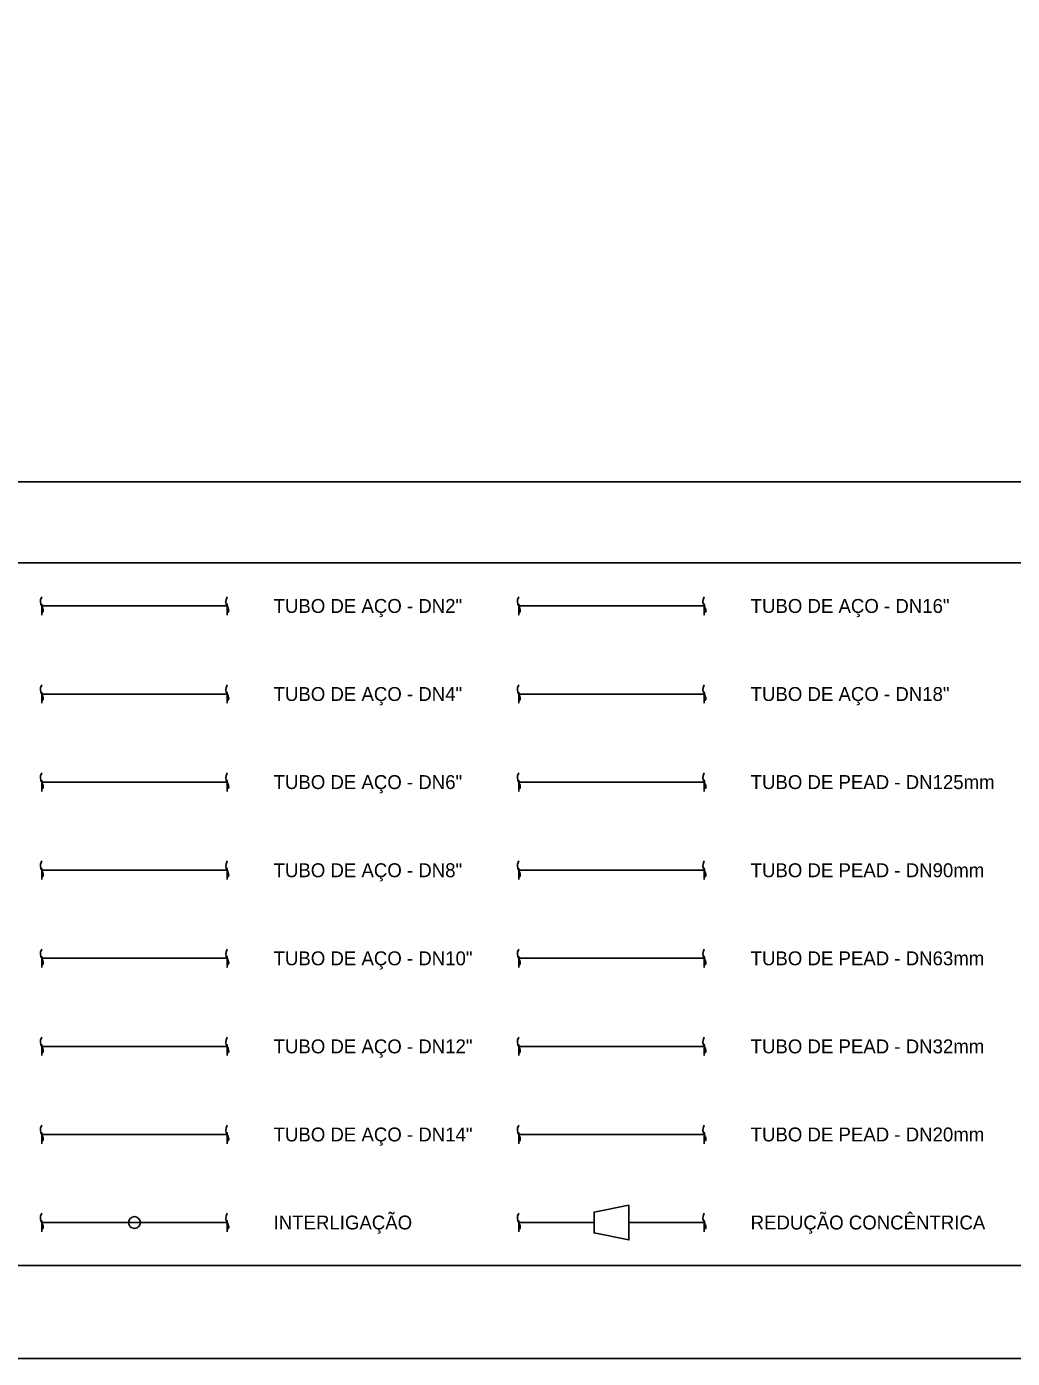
# Model space of a CAD drawing. Extents: x -1349 to -508, y 286 to 880.
# Drawn here: x -1137.7 to -1031.4, y 285.8 to 429.5 of the extents above; entities that cross this region are included whole.
import ezdxf

# ---------------------------------------------------------------- set-up
doc = ezdxf.new("R2010")
doc.units = 0
for name, color, linetype in [('FORMATO', 7, 'Continuous'), ('LEGENDA', 7, 'Continuous'), ('TUBO_ACO_GN_10', 7, 'Continuous'), ('TUBO_ACO_GN_12', 7, 'Continuous'), ('TUBO_ACO_GN_14', 7, 'Continuous'), ('TUBO_ACO_GN_16', 7, 'Continuous'), ('TUBO_ACO_GN_18', 7, 'Continuous'), ('TUBO_ACO_GN_2', 7, 'Continuous'), ('TUBO_ACO_GN_4', 7, 'Continuous'), ('TUBO_ACO_GN_6', 7, 'Continuous'), ('TUBO_ACO_GN_8', 7, 'Continuous'), ('TUBO_PEAD_GN_125', 7, 'Continuous'), ('TUBO_PEAD_GN_20', 7, 'Continuous'), ('TUBO_PEAD_GN_32', 7, 'Continuous'), ('TUBO_PEAD_GN_63', 7, 'Continuous'), ('TUBO_PEAD_GN_90', 7, 'Continuous')]:
    doc.layers.add(name, color=color, linetype=linetype)

msp = doc.modelspace()

# ---------------------------------------------------------------- linework, layer by layer
at = {"layer": 'FORMATO'}
msp.add_line((-518.04, 295.82), (-1344.05, 295.82), dxfattribs=at)
msp.add_lwpolyline([(-1349.05, 879.82), (-508.05, 879.82), (-508.05, 285.82), (-1349.05, 285.82)], close=True, dxfattribs=at)
for points in [[(-518.04, 380.36), (-1324.05, 380.36)], [(-1324.05, 371.63), (-693.05, 371.63)]]:
    msp.add_lwpolyline(points, dxfattribs=at)
at = {"layer": 'LEGENDA'}
msp.add_lwpolyline([(-1072.74, 302.34), (-1076.49, 301.59), (-1076.49, 299.34), (-1072.74, 298.59)], close=True, dxfattribs=at)
for points in [[(-1136.05, 300.47), (-1116.05, 300.47)], [(-1084.62, 300.47), (-1076.49, 300.47)], [(-1072.74, 300.47), (-1064.62, 300.47)]]:
    msp.add_lwpolyline(points, dxfattribs=at)
msp.add_circle((-1126.05, 300.47), 0.633, dxfattribs=at)
for points in [[(-1136.05, 301.47), (-1136.3, 300.97), (-1136.05, 300.47), (-1135.8, 299.97), (-1136.05, 299.47), (-1136.05, 301.47), (-1136.05, 299.47)], [(-1116.05, 301.47), (-1116.3, 300.97), (-1116.05, 300.47), (-1115.8, 299.97), (-1116.05, 299.47), (-1116.05, 301.47), (-1116.05, 299.47)], [(-1084.62, 301.47), (-1084.87, 300.97), (-1084.62, 300.47), (-1084.37, 299.97), (-1084.62, 299.47), (-1084.62, 301.47), (-1084.62, 299.47)], [(-1064.62, 301.47), (-1064.87, 300.97), (-1064.62, 300.47), (-1064.37, 299.97), (-1064.62, 299.47), (-1064.62, 301.47), (-1064.62, 299.47)]]:
    msp.add_open_spline(points, degree=3, dxfattribs=at)
at = {"layer": 'TUBO_ACO_GN_10'}
msp.add_lwpolyline([(-1136.05, 328.97), (-1116.05, 328.97)], dxfattribs=at)
for points in [[(-1136.05, 329.97), (-1136.3, 329.47), (-1136.05, 328.97), (-1135.8, 328.47), (-1136.05, 327.97), (-1136.05, 329.97), (-1136.05, 327.97)], [(-1116.05, 329.97), (-1116.3, 329.47), (-1116.05, 328.97), (-1115.8, 328.47), (-1116.05, 327.97), (-1116.05, 329.97), (-1116.05, 327.97)]]:
    msp.add_open_spline(points, degree=3, dxfattribs=at)
at = {"layer": 'TUBO_ACO_GN_12'}
msp.add_lwpolyline([(-1136.05, 319.47), (-1116.05, 319.47)], dxfattribs=at)
for points in [[(-1136.05, 320.47), (-1136.3, 319.97), (-1136.05, 319.47), (-1135.8, 318.97), (-1136.05, 318.47), (-1136.05, 320.47), (-1136.05, 318.47)], [(-1116.05, 320.47), (-1116.3, 319.97), (-1116.05, 319.47), (-1115.8, 318.97), (-1116.05, 318.47), (-1116.05, 320.47), (-1116.05, 318.47)]]:
    msp.add_open_spline(points, degree=3, dxfattribs=at)
at = {"layer": 'TUBO_ACO_GN_14'}
msp.add_lwpolyline([(-1136.05, 309.97), (-1116.05, 309.97)], dxfattribs=at)
for points in [[(-1136.05, 310.97), (-1136.3, 310.47), (-1136.05, 309.97), (-1135.8, 309.47), (-1136.05, 308.97), (-1136.05, 310.97), (-1136.05, 308.97)], [(-1116.05, 310.97), (-1116.3, 310.47), (-1116.05, 309.97), (-1115.8, 309.47), (-1116.05, 308.97), (-1116.05, 310.97), (-1116.05, 308.97)]]:
    msp.add_open_spline(points, degree=3, dxfattribs=at)
at = {"layer": 'TUBO_ACO_GN_16'}
msp.add_lwpolyline([(-1084.62, 366.98), (-1064.62, 366.98)], dxfattribs=at)
for points in [[(-1084.62, 367.98), (-1084.87, 367.48), (-1084.62, 366.98), (-1084.37, 366.48), (-1084.62, 365.98), (-1084.62, 367.98), (-1084.62, 365.98)], [(-1064.62, 367.98), (-1064.87, 367.48), (-1064.62, 366.98), (-1064.37, 366.48), (-1064.62, 365.98), (-1064.62, 367.98), (-1064.62, 365.98)]]:
    msp.add_open_spline(points, degree=3, dxfattribs=at)
at = {"layer": 'TUBO_ACO_GN_18'}
msp.add_lwpolyline([(-1084.62, 357.48), (-1064.62, 357.48)], dxfattribs=at)
for points in [[(-1084.62, 358.48), (-1084.87, 357.98), (-1084.62, 357.48), (-1084.37, 356.98), (-1084.62, 356.48), (-1084.62, 358.48), (-1084.62, 356.48)], [(-1064.62, 358.48), (-1064.87, 357.98), (-1064.62, 357.48), (-1064.37, 356.98), (-1064.62, 356.48), (-1064.62, 358.48), (-1064.62, 356.48)]]:
    msp.add_open_spline(points, degree=3, dxfattribs=at)
at = {"layer": 'TUBO_ACO_GN_2'}
msp.add_lwpolyline([(-1136.05, 366.98), (-1116.05, 366.98)], dxfattribs=at)
for points in [[(-1136.05, 367.98), (-1136.3, 367.48), (-1136.05, 366.98), (-1135.8, 366.48), (-1136.05, 365.98), (-1136.05, 367.98), (-1136.05, 365.98)], [(-1116.05, 367.98), (-1116.3, 367.48), (-1116.05, 366.98), (-1115.8, 366.48), (-1116.05, 365.98), (-1116.05, 367.98), (-1116.05, 365.98)]]:
    msp.add_open_spline(points, degree=3, dxfattribs=at)
at = {"layer": 'TUBO_ACO_GN_4'}
msp.add_lwpolyline([(-1136.05, 357.48), (-1116.05, 357.48)], dxfattribs=at)
for points in [[(-1136.05, 358.48), (-1136.3, 357.98), (-1136.05, 357.48), (-1135.8, 356.98), (-1136.05, 356.48), (-1136.05, 358.48), (-1136.05, 356.48)], [(-1116.05, 358.48), (-1116.3, 357.98), (-1116.05, 357.48), (-1115.8, 356.98), (-1116.05, 356.48), (-1116.05, 358.48), (-1116.05, 356.48)]]:
    msp.add_open_spline(points, degree=3, dxfattribs=at)
at = {"layer": 'TUBO_ACO_GN_6'}
msp.add_lwpolyline([(-1136.05, 347.98), (-1116.05, 347.98)], dxfattribs=at)
for points in [[(-1136.05, 348.98), (-1136.3, 348.48), (-1136.05, 347.98), (-1135.8, 347.48), (-1136.05, 346.98), (-1136.05, 348.98), (-1136.05, 346.98)], [(-1116.05, 348.98), (-1116.3, 348.48), (-1116.05, 347.98), (-1115.8, 347.48), (-1116.05, 346.98), (-1116.05, 348.98), (-1116.05, 346.98)]]:
    msp.add_open_spline(points, degree=3, dxfattribs=at)
at = {"layer": 'TUBO_ACO_GN_8'}
msp.add_lwpolyline([(-1136.05, 338.47), (-1116.05, 338.47)], dxfattribs=at)
for points in [[(-1136.05, 339.47), (-1136.3, 338.97), (-1136.05, 338.47), (-1135.8, 337.97), (-1136.05, 337.47), (-1136.05, 339.47), (-1136.05, 337.47)], [(-1116.05, 339.47), (-1116.3, 338.97), (-1116.05, 338.47), (-1115.8, 337.97), (-1116.05, 337.47), (-1116.05, 339.47), (-1116.05, 337.47)]]:
    msp.add_open_spline(points, degree=3, dxfattribs=at)
at = {"layer": 'TUBO_PEAD_GN_125'}
msp.add_lwpolyline([(-1084.62, 347.98), (-1064.62, 347.98)], dxfattribs=at)
for points in [[(-1084.62, 348.98), (-1084.87, 348.48), (-1084.62, 347.98), (-1084.37, 347.48), (-1084.62, 346.98), (-1084.62, 348.98), (-1084.62, 346.98)], [(-1064.62, 348.98), (-1064.87, 348.48), (-1064.62, 347.98), (-1064.37, 347.48), (-1064.62, 346.98), (-1064.62, 348.98), (-1064.62, 346.98)]]:
    msp.add_open_spline(points, degree=3, dxfattribs=at)
at = {"layer": 'TUBO_PEAD_GN_20'}
msp.add_lwpolyline([(-1084.62, 309.97), (-1064.62, 309.97)], dxfattribs=at)
for points in [[(-1084.62, 310.97), (-1084.87, 310.47), (-1084.62, 309.97), (-1084.37, 309.47), (-1084.62, 308.97), (-1084.62, 310.97), (-1084.62, 308.97)], [(-1064.62, 310.97), (-1064.87, 310.47), (-1064.62, 309.97), (-1064.37, 309.47), (-1064.62, 308.97), (-1064.62, 310.97), (-1064.62, 308.97)]]:
    msp.add_open_spline(points, degree=3, dxfattribs=at)
at = {"layer": 'TUBO_PEAD_GN_32'}
msp.add_lwpolyline([(-1084.62, 319.47), (-1064.62, 319.47)], dxfattribs=at)
for points in [[(-1084.62, 320.47), (-1084.87, 319.97), (-1084.62, 319.47), (-1084.37, 318.97), (-1084.62, 318.47), (-1084.62, 320.47), (-1084.62, 318.47)], [(-1064.62, 320.47), (-1064.87, 319.97), (-1064.62, 319.47), (-1064.37, 318.97), (-1064.62, 318.47), (-1064.62, 320.47), (-1064.62, 318.47)]]:
    msp.add_open_spline(points, degree=3, dxfattribs=at)
at = {"layer": 'TUBO_PEAD_GN_63'}
msp.add_lwpolyline([(-1084.62, 328.97), (-1064.62, 328.97)], dxfattribs=at)
for points in [[(-1084.62, 329.97), (-1084.87, 329.47), (-1084.62, 328.97), (-1084.37, 328.47), (-1084.62, 327.97), (-1084.62, 329.97), (-1084.62, 327.97)], [(-1064.62, 329.97), (-1064.87, 329.47), (-1064.62, 328.97), (-1064.37, 328.47), (-1064.62, 327.97), (-1064.62, 329.97), (-1064.62, 327.97)]]:
    msp.add_open_spline(points, degree=3, dxfattribs=at)
at = {"layer": 'TUBO_PEAD_GN_90'}
msp.add_lwpolyline([(-1084.62, 338.47), (-1064.62, 338.47)], dxfattribs=at)
for points in [[(-1084.62, 339.47), (-1084.87, 338.97), (-1084.62, 338.47), (-1084.37, 337.97), (-1084.62, 337.47), (-1084.62, 339.47), (-1084.62, 337.47)], [(-1064.62, 339.47), (-1064.87, 338.97), (-1064.62, 338.47), (-1064.37, 337.97), (-1064.62, 337.47), (-1064.62, 339.47), (-1064.62, 337.47)]]:
    msp.add_open_spline(points, degree=3, dxfattribs=at)

# ---------------------------------------------------------------- texts
at = {"layer": 'LEGENDA'}
for s, p in [('TUBO DE AÇO - DN2"', (-1111.05, 366.23)), ('TUBO DE AÇO - DN16"', (-1059.62, 366.23)), ('TUBO DE AÇO - DN4"', (-1111.05, 356.73)), ('TUBO DE AÇO - DN18"', (-1059.62, 356.73)), ('TUBO DE AÇO - DN6"', (-1111.05, 347.23)), ('TUBO DE PEAD - DN125mm', (-1059.62, 347.23)), ('TUBO DE AÇO - DN8"', (-1111.05, 337.72)), ('TUBO DE PEAD - DN90mm', (-1059.62, 337.72)), ('TUBO DE AÇO - DN10"', (-1111.05, 328.22)), ('TUBO DE PEAD - DN63mm', (-1059.62, 328.22)), ('TUBO DE AÇO - DN12"', (-1111.05, 318.72)), ('TUBO DE PEAD - DN32mm', (-1059.62, 318.72)), ('TUBO DE AÇO - DN14"', (-1111.05, 309.22)), ('TUBO DE PEAD - DN20mm', (-1059.62, 309.22)), ('INTERLIGAÇÃO', (-1111.05, 299.72)), ('REDUÇÃO CONCÊNTRICA', (-1059.62, 299.72))]:
    msp.add_text(s, height=1.5, dxfattribs=at).set_placement(p)

doc.saveas('drawing.dxf')
